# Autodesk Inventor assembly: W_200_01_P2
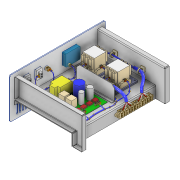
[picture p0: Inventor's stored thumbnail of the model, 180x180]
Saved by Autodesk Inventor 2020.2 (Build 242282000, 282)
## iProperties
Created: 2014-09
Part Number: W_200_01_P2
Document SubType Name: Assembly
Designer: F.Stasiak
Catalog Web Link: www.expertbooks.pl
Manager: www.cadconsulting.pl
Company: Fabian Stasiak CAD Consulting
Author: F.Stasiak
Subject: Zbiór ćwiczeń. Autodesk Inventor 2020. Kurs Professional
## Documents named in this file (19)
- C:\2020_Kurs_Professional\R2 Wiązki\W_200_01_P2.iam
- C:\2020_Kurs_Professional\R2 Wiązki\Komponenty\PCB_100_01.ipt
- C:\2020_Kurs_Professional\R2 Wiązki\Komponenty\S_150_100.ipt
- C:\2020_Kurs_Professional\R2 Wiązki\Komponenty\Switch_100_01.ipt
- C:\2020_Kurs_Professional\R2 Wiązki\Komponenty\Switch_100_02.ipt
- C:\2020_Kurs_Professional\R2 Wiązki\Komponenty\KOND_350_2300.ipt
- C:\2020_Kurs_Professional\R2 Wiązki\Komponenty\LAMP_100_01.ipt
- C:\2020_Kurs_Professional\R2 Wiązki\Komponenty\LISTWA_100_01.ipt
- C:\2020_Kurs_Professional\R2 Wiązki\Komponenty\Płyta.ipt
- C:\2020_Kurs_Professional\R2 Wiązki\Komponenty\Bok_01.ipt
- C:\2020_Kurs_Professional\R2 Wiązki\Komponenty\Bok_02.ipt
- C:\2020_Kurs_Professional\R2 Wiązki\Komponenty\Szyna_01.ipt
- C:\2020_Kurs_Professional\R2 Wiązki\Komponenty\Front_01.ipt
- C:\2020_Kurs_Professional\R2 Wiązki\Komponenty\METER_100_01.ipt
- C:\2020_Kurs_Professional\R2 Wiązki\Komponenty\Ściana_01.ipt
- C:\2020_Kurs_Professional\R2 Wiązki\Komponenty\KLIP_100_01.ipt
- C:\2020_Kurs_Professional\R2 Wiązki\W_200_01_P2\AIP\przewody i wiązki przewodów\W_200_01_P2.Wiązka przewodów1.iam
- C:\2020_Kurs_Professional\R2 Wiązki\W_200_01_P2\AIP\przewody i wiązki przewodów\W_200_01_P2.Wiązka przewodów2.iam
- C:\2020_Kurs_Professional\R2 Wiązki\W_200_01_P2\AIP\przewody i wiązki przewodów\W_200_01_P2.Wiązka przewodów3.iam
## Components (23 placed, 18 different names)
1. Płyta:1 — Równoległy:3, Zestawiający:1, Zestawiający:3, Zestawiający:4, Zestawiający:5, Zestawiający:6, Równoległy:4, Zestawiający:7, Zestawiający:8, Równoległy:5, Zestawiający:9, Równoległy:9, Równoległy:10, Zestawiający:13, Równoległy:14, Zestawiający:20, Równoległy:15
2. Bok_01:1 — Zestawiający:5, Zestawiający:6, Równoległy:4, Równoległy:11, Zestawiający:33, Zestawiający:34
3. Bok_02:1 — Zestawiający:7, Zestawiający:8, Równoległy:5
4. Szyna_01:1 — Zestawiający:9, Zestawiający:10, Równoległy:6, Równoległy:7, Zestawiający:11, Równoległy:14, Zestawiający:20
5. Ściana_01:1 — Równoległy:15, Zestawiający:30, Zestawiający:31
6. Front_01:1 — Równoległy:9, Równoległy:10, Zestawiający:13, Równoległy:11, Wstaw:1, Zestawiający:21, Zestawiający:22, Zestawiający:23, Zestawiający:24, Zestawiający:25, Zestawiający:26, Zestawiający:27, Zestawiający:28, Zestawiający:29
7. KLIP_100_01:1 — Zestawiający:30, Równoległy:16, Zestawiający:32, Równoległy:20, Równoległy:21
8. KLIP_100_01:2 — Zestawiający:31, Równoległy:16, Zestawiający:32, Równoległy:19, Równoległy:22
9. KLIP_100_01:3 — Zestawiający:33, Równoległy:19, Równoległy:22
10. KLIP_100_01:4 — Zestawiający:34, Równoległy:20, Równoległy:21
11. PCB_100_01:1 — Zestawiający:1
12. S_150_100:1 — Równoległy:1, Równoległy:2, Zestawiający:3
13. S_150_100:2 — Równoległy:1, Równoległy:2
14. LISTWA_100_01:1 — Zestawiający:4
15. Switch_100_01:1 — Zestawiający:23, Zestawiający:24, Zestawiający:26
16. Switch_100_02:1 — Zestawiający:21, Zestawiający:22, Zestawiający:25
17. KOND_350_2300:1 — Zestawiający:10, Równoległy:6, Równoległy:7, Równoległy:8, Zestawiający:12
18. KOND_350_2300:2 — Zestawiający:11, Równoległy:8, Zestawiający:12
19. LAMP_100_01:1 — Wstaw:1
20. METER_100_01:1 — Zestawiający:27, Zestawiający:28, Zestawiający:29
21. Wiązka przewodów1 [sub-assembly]
22. Wiązka przewodów2 [sub-assembly]
23. Wiązka przewodów3 [sub-assembly]
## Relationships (46: Mate 27, Flush 18, Insert 1)
- Równoległy:1 [Flush]: S_150_100:1 ↔ S_150_100:2
- Równoległy:2 [Flush]: S_150_100:1 ↔ S_150_100:2
- Równoległy:3 [Flush]: Płyta:1
- Zestawiający:1 [Mate]: Płyta:1 ↔ PCB_100_01:1
- Zestawiający:3 [Mate]: Płyta:1 ↔ S_150_100:1
- Zestawiający:4 [Mate]: Płyta:1 ↔ LISTWA_100_01:1
- Zestawiający:5 [Mate]: Płyta:1 ↔ Bok_01:1
- Zestawiający:6 [Mate]: Płyta:1 ↔ Bok_01:1
- Równoległy:4 [Flush]: Płyta:1 ↔ Bok_01:1
- Zestawiający:7 [Mate]: Płyta:1 ↔ Bok_02:1
- Zestawiający:8 [Mate]: Płyta:1 ↔ Bok_02:1
- Równoległy:5 [Flush]: Płyta:1 ↔ Bok_02:1
- Zestawiający:9 [Mate]: Płyta:1 ↔ Szyna_01:1
- Zestawiający:10 [Mate]: Szyna_01:1 ↔ KOND_350_2300:1
- Równoległy:6 [Flush]: Szyna_01:1 ↔ KOND_350_2300:1
- Równoległy:7 [Flush]: Szyna_01:1 ↔ KOND_350_2300:1
- Zestawiający:11 [Mate]: Szyna_01:1 ↔ KOND_350_2300:2
- Równoległy:8 [Flush]: KOND_350_2300:1 ↔ KOND_350_2300:2
- Zestawiający:12 [Mate]: KOND_350_2300:1 ↔ KOND_350_2300:2
- Równoległy:9 [Flush]: Płyta:1 ↔ Front_01:1
- Równoległy:10 [Flush]: Płyta:1 ↔ Front_01:1
- Zestawiający:13 [Mate]: Płyta:1 ↔ Front_01:1
- Równoległy:11 [Flush]: Bok_01:1 ↔ Front_01:1
- Równoległy:14 [Flush]: Płyta:1 ↔ Szyna_01:1
- Zestawiający:20 [Mate]: Płyta:1 ↔ Szyna_01:1
- Wstaw:1 [Insert]: Front_01:1 ↔ LAMP_100_01:1
- Zestawiający:21 [Mate]: Front_01:1 ↔ Switch_100_02:1
- Zestawiający:22 [Mate]: Front_01:1 ↔ Switch_100_02:1
- Zestawiający:23 [Mate]: Front_01:1 ↔ Switch_100_01:1
- Zestawiający:24 [Mate]: Front_01:1 ↔ Switch_100_01:1
- Zestawiający:25 [Mate]: Front_01:1 ↔ Switch_100_02:1
- Zestawiający:26 [Mate]: Front_01:1 ↔ Switch_100_01:1
- Zestawiający:27 [Mate]: Front_01:1 ↔ METER_100_01:1
- Zestawiający:28 [Mate]: Front_01:1 ↔ METER_100_01:1
- Zestawiający:29 [Mate]: Front_01:1 ↔ METER_100_01:1
- Równoległy:15 [Flush]: Płyta:1 ↔ Ściana_01:1
- Zestawiający:30 [Mate]: Ściana_01:1 ↔ KLIP_100_01:1
- Zestawiający:31 [Mate]: Ściana_01:1 ↔ KLIP_100_01:2
- Równoległy:16 [Flush]: KLIP_100_01:1 ↔ KLIP_100_01:2
- Zestawiający:32 [Mate]: KLIP_100_01:1 ↔ KLIP_100_01:2
- Zestawiający:33 [Mate]: Bok_01:1 ↔ KLIP_100_01:3
- Zestawiający:34 [Mate]: Bok_01:1 ↔ KLIP_100_01:4
- Równoległy:19 [Flush]: KLIP_100_01:2 ↔ KLIP_100_01:3
- Równoległy:20 [Flush]: KLIP_100_01:1 ↔ KLIP_100_01:4
- Równoległy:21 [Flush]: KLIP_100_01:1 ↔ KLIP_100_01:4
- Równoległy:22 [Flush]: KLIP_100_01:2 ↔ KLIP_100_01:3
